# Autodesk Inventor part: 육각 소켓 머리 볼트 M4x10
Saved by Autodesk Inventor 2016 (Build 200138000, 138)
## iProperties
Created: 2024-08
Part Number: 육각 소켓 머리 볼트 M4x10
Material: 일반
Description: 6각머리 태핑 나사
Document SubType Name: Modeling
Designer: pc-2
Density: 1 g/cm^3
Appearance: 기본값
Author: jhkim
Sending System: Autodesk Inventor 2025
Preprocessor: ST-DEVELOPER v20
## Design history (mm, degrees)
node "육각 소켓 머리 볼트 M4x101"
node "솔리드1"
body "Solid1"
